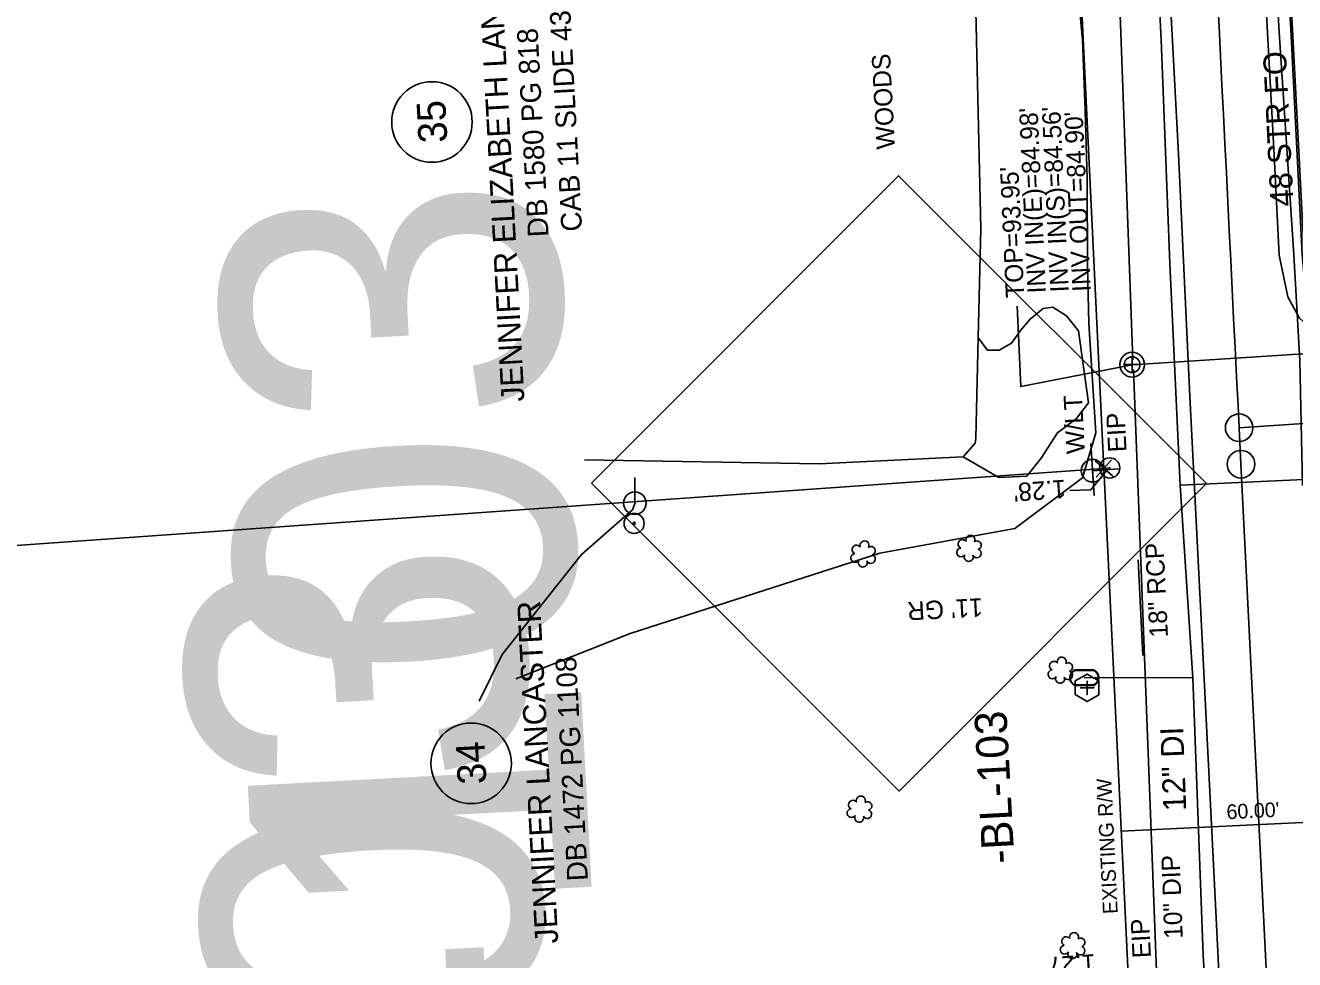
# Model space of a CAD drawing. Extents: x 2364404 to 2371833, y 798876 to 809754.
# Drawn here: x 2368599.6 to 2368875.6, y 803106.5 to 803309.6 of the extents above; entities that cross this region are included whole.
import ezdxf

# ---------------------------------------------------------------- set-up
doc = ezdxf.new("R2010")
doc.units = 0
for name, color, linetype in [('CTL Supplemental Horizontal and Vertical CELL', 7, 'Continuous'), ('Exist Horizontal Alignment Direction Label', 7, 'Continuous'), ('Exist Horizontal Alignment Point', 7, 'Continuous'), ('Exist Horizontal Baseline Alignment Station Label', 7, 'Continuous'), ('Exist Other Culture Located Object CELL', 7, 'Continuous'), ('Exist Property Corner CELL', 7, 'Continuous'), ('Exist Property Deed Book Text', 7, 'Continuous'), ('Exist Property Iron Pin CELL', 7, 'Continuous'), ('Exist Property Iron Pin Text', 7, 'Continuous'), ('Exist Property Line', 7, 'Continuous'), ('Exist Property Line Leader', 7, 'Continuous'), ('Exist Property Line Text', 7, 'Continuous'), ('Exist Property Owner Number CELL', 7, 'Continuous'), ('Exist Property Owner Text', 7, 'Continuous'), ('Exist Right of Way Line', 7, 'Continuous'), ('Exist Right of Way Line Text', 7, 'Continuous'), ('Exist Right of Way Width CELL', 7, 'Continuous'), ('Exist Roads EOP', 7, 'Continuous'), ('Exist Roads Soil Text', 7, 'Continuous'), ('Exist Structure Minor Pipes RCP 18 Inch', 7, 'Continuous'), ('Exist Structure Minor Pipes RCP 18 Inch Text', 7, 'Continuous'), ('Exist Utilities Gas UG Line SUE LOS B', 7, 'Continuous'), ('Exist Utilities Power Joint Use Telephone CELL', 7, 'Continuous'), ('Exist Utilities Power Joint Use Telephone Text', 7, 'Continuous'), ('Exist Utilities Power Pole CELL', 7, 'Continuous'), ('Exist Utilities Power UG Cable SUE LOS B', 7, 'Continuous'), ('Exist Utilities Sanitary Sewer Clean-Out CELL', 7, 'Continuous'), ('Exist Utilities Sanitary Sewer Manhole CELL', 7, 'Continuous'), ('Exist Utilities Sanitary Sewer Manhole Leader', 7, 'Continuous'), ('Exist Utilities Sanitary Sewer Manhole Top Elevation', 7, 'Continuous'), ('Exist Utilities Sanitary Sewer UG Line', 7, 'Continuous'), ('Exist Utilities Sanitary Sewer UG Line Invert Elevation', 7, 'Continuous'), ('Exist Utilities Sanitary Sewer UG Line Text', 7, 'Continuous'), ('Exist Utilities Telephone UG Cable SUE LOS C', 7, 'Continuous'), ('Exist Utilities Telephone UG FO SUE LOS B', 7, 'Continuous'), ('Exist Utilities Telephone UG FO SUE LOS B Text', 7, 'Continuous'), ('Exist Utilities Water Meter CELL', 7, 'Continuous'), ('Exist Utilities Water UG Line SUE LOS B', 7, 'Continuous'), ('Exist Utilities Water UG Line SUE LOS B Text', 7, 'Continuous'), ('Exist Vegetation Hedge Row', 7, 'Continuous'), ('Exist Vegetation Shrub CELL', 7, 'Continuous'), ('Exist Vegetation Woods Line', 7, 'Continuous'), ('Exist Vegetation Woods Line Text', 7, 'Continuous'), ('Prop Horizontal Alignment', 7, 'Continuous')]:
    doc.layers.add(name, color=color, linetype=linetype)

msp = doc.modelspace()

# ---------------------------------------------------------------- linework, layer by layer
at = {"layer": 'CTL Supplemental Horizontal and Vertical CELL'}
msp.add_line((2368789.15, 803209.88), (2368789.15, 803209.88), dxfattribs=at)
msp.add_lwpolyline([(2368722.66, 803210.1), (2368789.48, 803276.93), (2368856.42, 803209.99), (2368789.6, 803143.16)], close=True, dxfattribs=at)
at = {"layer": 'Exist Horizontal Alignment Point'}
for centre in [(2368863.54, 803222.15), (2368863.94, 803214.22)]:
    msp.add_circle(centre, 3, dxfattribs=at)
at = {"layer": 'Exist Other Culture Located Object CELL'}
for radius in [2.18, 0.24]:
    msp.add_circle((2368731.96, 803201.35), radius, dxfattribs=at)
at = {"layer": 'Exist Property Corner CELL'}
msp.add_line((2368834.11, 803213.31), (2368834.11, 803213.31), dxfattribs=at)
msp.add_lwpolyline([(2368835.75, 803215.2), (2368832.47, 803211.43), (2368834.11, 803213.31), (2368836, 803211.68), (2368832.22, 803214.95)], dxfattribs=at)
at = {"layer": 'Exist Property Iron Pin CELL'}
for radius in [2.2, 0.0707]:
    msp.add_circle((2368835.39, 803213.4), radius, dxfattribs=at)
at = {"layer": 'Exist Property Line'}
for p, q in [((2368073.89, 803159.45), (2368834.11, 803213.31)), ((2368834.11, 803213.31), (2368835.39, 803213.4))]:
    msp.add_line(p, q, dxfattribs=at)
at = {"layer": 'Exist Property Line Leader'}
msp.add_lwpolyline([(2368834.9, 803213.09), (2368831.28, 803208.66), (2368826.74, 803208.47)], dxfattribs=at)
at = {"layer": 'Exist Property Owner Number CELL'}
for centre in [(2368687.98, 803288.63), (2368696.5, 803149.17)]:
    msp.add_circle(centre, 8.75, dxfattribs=at)
at = {"layer": 'Exist Right of Way Line'}
msp.add_line((2368861.79, 802635.55), (2368816.68, 803577.19), dxfattribs=at)
at = {"layer": 'Exist Right of Way Width CELL'}
for p in [(2368897.82, 803137.26), (2368837.89, 803134.39)]:
    msp.add_line(p, (2368868.16, 803135.84), dxfattribs=at)
at = {"layer": 'Exist Roads EOP'}
for points in [[(2368858.04, 803594.67), (2368855.98, 803588.19), (2368857.75, 803548.6), (2368860.49, 803495.61), (2368862.97, 803442.05), (2368865.73, 803387.31), (2368868.22, 803336.07), (2368871.09, 803282.81), (2368872.26, 803259.71), (2368874.13, 803250.63), (2368876.67, 803246.01), (2368884.04, 803239.28), (2368889.64, 803236.25), (2368898, 803235.19), (2368924.38, 803236.19), (2368927.42, 803236.83), (2368927.95, 803239.13), (2368941.24, 803239.86), (2368941.79, 803237.79), (2368941.91, 803237.22), (2368978.75, 803239.68), (2369030.43, 803243.44), (2369080.69, 803246.97), (2369130.52, 803250.09)], [(2368873.49, 802792.49), (2368871.21, 802843.9), (2368868.93, 802899.23), (2368866.3, 802955.07), (2368863.66, 803010.2), (2368861.02, 803065.7), (2368858.22, 803121.37), (2368855.49, 803176.21), (2368852.81, 803229.03), (2368850.32, 803281.64), (2368847.49, 803334.78)]]:
    msp.add_lwpolyline(points, dxfattribs=at)
at = {"layer": 'Exist Structure Minor Pipes RCP 18 Inch'}
msp.add_line((2368841.61, 803193.44), (2368842.61, 803172.64), dxfattribs=at)
at = {"layer": 'Exist Utilities Gas UG Line SUE LOS B'}
msp.add_lwpolyline([(2368877.35, 803209.61), (2368876.73, 803236.75), (2368875.47, 803259.74), (2368872.24, 803308.15), (2368869.52, 803357.59), (2368867.05, 803407.9), (2368865, 803456.99), (2368863.75, 803482.79), (2368862.16, 803506.14), (2368860.89, 803556.81), (2368858.96, 803592.82), (2368858.1, 803605.88), (2368857.92, 803607.82), (2368855.51, 803656.69)], dxfattribs=at)
at = {"layer": 'Exist Utilities Power Joint Use Telephone CELL'}
msp.add_line((2368831.66, 803212.81), (2368831.66, 803212.81), dxfattribs=at)
msp.add_lwpolyline([(2368831.27, 803218.73), (2368831.98, 803207.42), (2368831.64, 803212.81), (2368837.27, 803213.18)], dxfattribs=at)
msp.add_circle((2368831.66, 803212.81), 2.45, dxfattribs=at)
at = {"layer": 'Exist Utilities Power Pole CELL'}
for q in [(2368732.09, 803211.36), (2368732.09, 803205.74)]:
    msp.add_line((2368732.09, 803205.74), q, dxfattribs=at)
msp.add_circle((2368732.09, 803205.74), 2.45, dxfattribs=at)
at = {"layer": 'Exist Utilities Power UG Cable SUE LOS B'}
msp.add_lwpolyline([(2368698.22, 803162.69), (2368703.29, 803172.83), (2368720.54, 803194.61), (2368731.6, 803204.29), (2368732.18, 803205.84)], dxfattribs=at)
at = {"layer": 'Exist Utilities Sanitary Sewer Clean-Out CELL'}
msp.add_line((2368830.46, 803165.6), (2368830.46, 803165.6), dxfattribs=at)
msp.add_lwpolyline([(2368827.88, 803167.09), (2368827.88, 803164.11), (2368830.46, 803162.62), (2368833.04, 803164.1), (2368833.04, 803167.08), (2368830.47, 803168.58)], close=True, dxfattribs=at)
msp.add_lwpolyline([(2368830.46, 803167.11), (2368830.46, 803164.08), (2368830.46, 803165.6), (2368831.97, 803165.6), (2368828.95, 803165.6)], dxfattribs=at)
at = {"layer": 'Exist Utilities Sanitary Sewer Manhole CELL'}
msp.add_lwpolyline([(2368840.27, 803237.58), (2368840.27, 803234.15), (2368840.27, 803235.87), (2368841.99, 803235.87), (2368838.56, 803235.87)], dxfattribs=at)
for radius in [2.69, 1.71]:
    msp.add_circle((2368840.27, 803235.87), radius, dxfattribs=at)
at = {"layer": 'Exist Utilities Sanitary Sewer Manhole Leader'}
msp.add_lwpolyline([(2368840.26, 803235.85), (2368816.04, 803231.1), (2368815.24, 803248.59)], dxfattribs=at)
at = {"layer": 'Exist Utilities Sanitary Sewer UG Line'}
for p, q in [((2368840.39, 803236.89), (2368827.1, 803604.31)), ((2368841.41, 803235.89), (2369134.72, 803254.99)), ((2368852.54, 802922.33), (2368840.54, 803234.78))]:
    msp.add_line(p, q, dxfattribs=at)
at = {"layer": 'Exist Utilities Telephone UG Cable SUE LOS C'}
msp.add_lwpolyline([(2368706.25, 803167.56), (2368731.06, 803177.38), (2368785.4, 803194.88), (2368814.77, 803200.26), (2368829.51, 803211.28), (2368832.35, 803221.03), (2368830.85, 803244.85), (2368830.57, 803257.19), (2368830.48, 803276.29), (2368830.06, 803291.13), (2368829.47, 803306.5), (2368827.18, 803331.1), (2368824.55, 803347.88), (2368822.3, 803365.97), (2368823.19, 803375.44), (2368824.11, 803375.88)], dxfattribs=at)
at = {"layer": 'Exist Utilities Telephone UG FO SUE LOS B'}
for points in [[(2368882.02, 803210.12), (2368877.65, 803259.87), (2368875.13, 803308.78), (2368872.36, 803358.1), (2368869.94, 803407.98), (2368868.02, 803457.37), (2368865.26, 803507.05), (2368862.66, 803556.84), (2368861.52, 803606.08), (2368859.12, 803656.15), (2368855.83, 803706.12), (2368853.22, 803755.12), (2368850.83, 803804.74)], [(2368881.62, 803210.2), (2368877.23, 803259.82), (2368874.79, 803308.73), (2368871.77, 803357.86), (2368869.41, 803407.86), (2368867.52, 803457.45), (2368864.76, 803506.88), (2368861.94, 803556.71), (2368861.04, 803605.91), (2368858.64, 803656.12)]]:
    msp.add_lwpolyline(points, dxfattribs=at)
at = {"layer": 'Exist Utilities Water Meter CELL'}
msp.add_line((2368829.86, 803167.8), (2368829.86, 803167.8), dxfattribs=at)
for points in [[(2368827.81, 803169.48), (2368831.88, 803169.51)], [(2368827.81, 803169.34), (2368831.88, 803169.38)], [(2368831.91, 803166.25), (2368827.81, 803166.22)], [(2368831.91, 803166.11), (2368827.81, 803166.08)]]:
    msp.add_lwpolyline(points, dxfattribs=at)
for centre, radius, start, end in [((2368831.15, 803167.81), 1.86, 294.1414, 66.8015), ((2368828.55, 803167.78), 1.86, 113.6712, 246.4725), ((2368828.56, 803167.78), 1.73, 115.7941, 244.2755), ((2368831.16, 803167.81), 1.73, 295.6203, 65.3659)]:
    msp.add_arc(centre, radius, start, end, dxfattribs=at)
at = {"layer": 'Exist Utilities Water UG Line SUE LOS B'}
for points in [[(2368848.45, 803257.88), (2368846.55, 803306.48), (2368844.07, 803356.52), (2368841.69, 803400.26), (2368837.48, 803455.45), (2368836.41, 803472.08), (2368836.1, 803483.59), (2368835.09, 803505), (2368833.58, 803555.34), (2368831.52, 803604.76), (2368831.17, 803634.09)], [(2368870.85, 802794.34), (2368867.73, 802859.98), (2368865.33, 802913.72), (2368861.58, 803008.74), (2368860.05, 803042.36), (2368858.64, 803059.24), (2368855.73, 803107.44), (2368853.47, 803167.78), (2368850.72, 803209.61), (2368848.45, 803257.88)], [(2368850.72, 803209.61), (2368850.85, 803209.63), (2368885.57, 803211.24)], [(2368829.86, 803167.8), (2368830.41, 803167.85), (2368853.47, 803167.78)]]:
    msp.add_lwpolyline(points, dxfattribs=at)
at = {"layer": 'Exist Vegetation Hedge Row'}
msp.add_lwpolyline([(2368806.79, 803241.67), (2368808.83, 803239.01), (2368811.32, 803239), (2368814.01, 803240.57), (2368816, 803243.3), (2368818.09, 803245.77), (2368820.92, 803248.07), (2368823, 803248.36), (2368825.99, 803246.5), (2368828.57, 803243.21), (2368830.79, 803227.57), (2368828.14, 803224.16), (2368824.02, 803221.02), (2368820.52, 803215.54), (2368817.35, 803211.65), (2368811.27, 803211.31), (2368803.52, 803215.86)], dxfattribs=at)
at = {"layer": 'Exist Vegetation Shrub CELL'}
for p, q in [((2368781.82, 803194.52), (2368781.82, 803194.52)), ((2368804.87, 803195.74), (2368804.87, 803195.74)), ((2368824.73, 803169.24), (2368824.73, 803169.24)), ((2368781.04, 803139.04), (2368781.04, 803139.04)), ((2368827.41, 803109.36), (2368827.41, 803109.36))]:
    msp.add_line(p, q, dxfattribs=at)
for centre, radius, start, end in [((2368782.05, 803196.56), 0.99, 334.8391, 200.4717), ((2368803.38, 803196.87), 0.968, 35.8908, 245.4216), ((2368805.09, 803197.79), 0.99, 334.8391, 200.4717), ((2368806.54, 803196.61), 0.929, 284.4567, 126.0861), ((2368780.02, 803193.82), 0.955, 95.1099, 327.9534), ((2368780.33, 803195.65), 0.968, 35.8908, 245.4216), ((2368783.45, 803193.59), 0.937, 204.9913, 73.4601), ((2368783.49, 803195.39), 0.929, 284.4567, 126.0861), ((2368803.07, 803195.04), 0.955, 95.1099, 327.9534), ((2368804.74, 803194.06), 0.984, 151.2797, 21.387), ((2368806.5, 803194.82), 0.937, 204.9913, 73.4601), ((2368781.69, 803192.84), 0.984, 151.2797, 21.387), ((2368824.96, 803171.28), 0.99, 334.8391, 200.4717), ((2368822.93, 803168.54), 0.955, 95.1099, 327.9534), ((2368823.25, 803170.37), 0.968, 35.8908, 245.4216), ((2368826.4, 803170.11), 0.929, 284.4567, 126.0861), ((2368824.6, 803167.56), 0.984, 151.2797, 21.387), ((2368826.37, 803168.31), 0.937, 204.9913, 73.4601), ((2368781.26, 803141.08), 0.99, 334.8391, 200.4717), ((2368779.23, 803138.34), 0.955, 95.1099, 327.9534), ((2368779.55, 803140.17), 0.968, 35.8908, 245.4216), ((2368782.71, 803139.91), 0.929, 284.4567, 126.0861), ((2368780.91, 803137.36), 0.984, 151.2797, 21.387), ((2368782.67, 803138.11), 0.937, 204.9913, 73.4601), ((2368827.63, 803111.4), 0.99, 334.8391, 200.4717), ((2368825.6, 803108.66), 0.955, 95.1099, 327.9534), ((2368825.92, 803110.49), 0.968, 35.8908, 245.4216), ((2368829.04, 803108.43), 0.937, 204.9913, 73.4601), ((2368829.08, 803110.23), 0.929, 284.4567, 126.0861), ((2368827.28, 803107.68), 0.984, 151.2797, 21.387)]:
    msp.add_arc(centre, radius, start, end, dxfattribs=at)
at = {"layer": 'Exist Vegetation Woods Line'}
for points in [[(2368712.32, 803331.44), (2368723.61, 803331.49), (2368733.72, 803331.99), (2368741.85, 803333.11), (2368751.06, 803336.57), (2368768.77, 803342.66), (2368778.18, 803343.77), (2368788.06, 803345.81), (2368794.75, 803346.01), (2368800.83, 803343.31), (2368804.4, 803338.02), (2368806.07, 803322.32), (2368807.33, 803265.47), (2368806.79, 803241.67)], [(2368806.79, 803241.67), (2368806.29, 803219.86), (2368806.12, 803218.79), (2368803.52, 803215.86), (2368772.21, 803214.28), (2368721.13, 803215.18)]]:
    msp.add_lwpolyline(points, dxfattribs=at)
at = {"layer": 'Prop Horizontal Alignment'}
for p, q in [((2368863.54, 803222.15), (2369130.81, 803240.22)), ((2368870.72, 803079.11), (2368863.94, 803214.22))]:
    msp.add_line(p, q, dxfattribs=at)
msp.add_arc((2677047.33, 818679.94), 308571.21, 182.7974457, 182.8728926, dxfattribs=at)

# ---------------------------------------------------------------- texts
at = {"layer": 'Exist Horizontal Alignment Direction Label'}
msp.add_text('BL-103', height=73.5, rotation=93.6251, dxfattribs=at).set_placement((2368726.45, 802883.38))
at = {"layer": 'Exist Horizontal Baseline Alignment Station Label'}
for s, height, p in [('BL-103', 73.5, (2368731.27, 802962.13)), ('-BL-103', 7, (2368814.7, 803127.5))]:
    msp.add_text(s, height=height, rotation=93.0566, dxfattribs=at).set_placement(p)
at = {"layer": 'Exist Property Deed Book Text'}
for s, p in [('CAB 11 SLIDE 43', (2368720.65, 803264.93)), ('DB 1580 PG 818', (2368713.37, 803263.72)), ('DB 1472 PG 1108', (2368721.91, 803123.69))]:
    msp.add_text(s, height=4.5, rotation=93.0566, dxfattribs=at).set_placement(p)
at = {"layer": 'Exist Property Iron Pin Text'}
for p in [(2368839.07, 803216.94), (2368844.38, 803106.93)]:
    msp.add_text('EIP', height=4, rotation=93.0566, dxfattribs=at).set_placement(p)
at = {"layer": 'Exist Property Line Text'}
for s, p in [("1.28'", (2368825.74, 803210.87)), ("1.27'", (2368832.19, 803107.72))]:
    msp.add_text(s, height=4, rotation=184.053, dxfattribs=at).set_placement(p)
at = {"layer": 'Exist Property Owner Number CELL'}
for s, p in [('35', (2368691.35, 803284.23)), ('34', (2368699.86, 803144.77))]:
    msp.add_text(s, height=6.25, rotation=93.0566, dxfattribs=at).set_placement(p)
at = {"layer": 'Exist Property Owner Text'}
for s, p in [('JENNIFER ELIZABETH LANCASTER', (2368708.11, 803227.92)), ('JENNIFER LANCASTER', (2368715.47, 803110.08))]:
    msp.add_text(s, height=5, rotation=93.0566, dxfattribs=at).set_placement(p)
at = {"layer": 'Exist Right of Way Line Text'}
msp.add_text('EXISTING R/W', height=3.2, rotation=92.7428, dxfattribs=at).set_placement((2368837.14, 803116.5))
at = {"layer": 'Exist Right of Way Width CELL'}
msp.add_text("60.00'", height=3.2, rotation=2.7428, dxfattribs=at).set_placement((2368860.86, 803137.01))
at = {"layer": 'Exist Roads Soil Text'}
msp.add_text("11' GR", height=4, rotation=183.0278, dxfattribs=at).set_placement((2368807.69, 803185.11))
at = {"layer": 'Exist Structure Minor Pipes RCP 18 Inch Text'}
msp.add_text('18" RCP', height=4, rotation=92.7607, dxfattribs=at).set_placement((2368848.07, 803176.63))
at = {"layer": 'Exist Utilities Power Joint Use Telephone Text'}
msp.add_text('W/LT', height=4, rotation=93.0566, dxfattribs=at).set_placement((2368830.02, 803216.58))
at = {"layer": 'Exist Utilities Sanitary Sewer Manhole Top Elevation'}
msp.add_text("TOP=93.95'", height=4, rotation=92.6184, dxfattribs=at).set_placement((2368816.82, 803250.49))
at = {"layer": 'Exist Utilities Sanitary Sewer UG Line Invert Elevation'}
for s, p in [("INV IN(E)=84.98'", (2368821.53, 803251.46)), ("INV IN(S)=84.56'", (2368826.47, 803251.69)), ("INV OUT=84.90'", (2368831.29, 803251.81))]:
    msp.add_text(s, height=4, rotation=92.6184, dxfattribs=at).set_placement(p)
at = {"layer": 'Exist Utilities Sanitary Sewer UG Line Text'}
msp.add_text('10" DIP', height=4, rotation=92.1988, dxfattribs=at).set_placement((2368851.29, 803111.08))
at = {"layer": 'Exist Utilities Telephone UG FO SUE LOS B Text'}
msp.add_text('48 STR FO', height=5, rotation=92.8602, dxfattribs=at).set_placement((2368875.39, 803270.37))
at = {"layer": 'Exist Utilities Water UG Line SUE LOS B Text'}
msp.add_text('12" DI', height=5, rotation=92.1471, dxfattribs=at).set_placement((2368852.05, 803138.86))
at = {"layer": 'Exist Vegetation Woods Line Text'}
msp.add_text('WOODS', height=4, rotation=93.0566, dxfattribs=at).set_placement((2368788.71, 803282.82))

doc.saveas('drawing.dxf')
